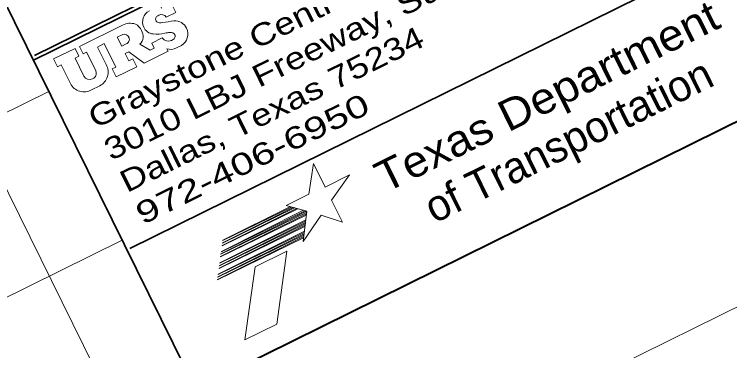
# Model space of a CAD drawing. Extents: x 2356606 to 2371222, y 6973096 to 6982644.
# Drawn here: x 2370176.5 to 2370607.9, y 6979196 to 6979398.7 of the extents above; entities that cross this region are included whole.
import ezdxf
from ezdxf.enums import TextEntityAlignment as Align

# ---------------------------------------------------------------- set-up
doc = ezdxf.new("R2010")
doc.units = 0
doc.header["$LTSCALE"] = 2
doc.layers.add('62', color=7, linetype='Continuous', lineweight=13)
doc.layers.add('63', color=7, linetype='Continuous', lineweight=13)

msp = doc.modelspace()

# ---------------------------------------------------------------- linework, layer by layer
at = {"layer": '62'}
for p, q in [((2369622.333, 6980406.659), (2370241.954, 6979151.173)), ((2371003.634, 6979415.568), (2358199.427, 6973096.266)), ((2370263.665, 6979398.139), (2370263.05, 6979397.836)), ((2370238.606, 6979384.905), (2370241.982, 6979386.571)), ((2370271.275, 6979382.972), (2370272.335, 6979383.54)), ((2370277.258, 6979379.982), (2370274.268, 6979378.507)), ((2370223.616, 6979359.868), (2370224.388, 6979360.249)), ((2370197.388, 6979352.221), (2358740.123, 6973697.678)), ((2370228.034, 6979355.685), (2370223.054, 6979353.231)), ((2370241.647, 6979262.543), (2358784.382, 6973608.002))]:
    msp.add_line(p, q, dxfattribs=at)
at = {"layer": '62', "lineweight": 35}
for p, q in [((2370021.757, 6979708.087), (2370285.907, 6979172.864)), ((2370772.563, 6979661.979), (2370188.769, 6979373.856)), ((2370601.161, 6979432.671), (2370246.201, 6979257.487))]:
    msp.add_line(p, q, dxfattribs=at)
at = {"layer": '62', "lineweight": 40}
msp.add_line((2370869.698, 6979460.986), (2358244.847, 6973230.201), dxfattribs=at)
at = {"layer": '62'}
for points in [[(2370265.161, 6979402.489), (2370265.378, 6979402.596), (2370264.774, 6979403.82), (2370270.561, 6979406.676), (2370273.942, 6979399.825), (2370268.155, 6979396.969)], [(2370225.423, 6979365.199), (2370220.137, 6979375.91), (2370218.015, 6979374.863), (2370215.777, 6979379.398), (2370241.818, 6979392.25)], [(2370244.07, 6979380.882), (2370241.273, 6979379.502), (2370238.606, 6979384.905)], [(2370252.242, 6979380.739), (2370258.53, 6979377.099), (2370260.942, 6979378.289), (2370259.418, 6979381.377), (2370265.783, 6979384.519)], [(2370210.421, 6979356.956), (2370204.849, 6979368.245), (2370202.534, 6979367.103), (2370200.201, 6979371.831), (2370213.125, 6979378.209), (2370215.458, 6979373.481), (2370213.143, 6979372.339), (2370218.525, 6979361.435)], [(2370268.541, 6979377.96), (2370269.303, 6979376.416), (2370254.835, 6979369.276), (2370245.489, 6979376.063), (2370243.463, 6979375.063), (2370245.654, 6979370.625), (2370248.065, 6979371.815), (2370250.399, 6979367.086), (2370237.957, 6979360.946), (2370235.576, 6979365.771), (2370237.794, 6979366.865), (2370230.794, 6979381.05), (2370226.646, 6979379.003), (2370231.885, 6979368.389)]]:
    msp.add_lwpolyline(points, dxfattribs=at)
for points in [[(2370356.998, 6979308.703), (2370354.183, 6979290.219), (2370340.423, 6979283.426), (2370352.86, 6979280.022), (2370350.698, 6979261.838), (2370361.606, 6979277.578), (2370374.364, 6979273.517), (2370367.885, 6979286.641), (2370378.66, 6979301.888), (2370363.949, 6979294.619)], [(2370301.158, 6979254.309), (2370352.651, 6979280.053), (2370352.85, 6979280.014), (2370352.756, 6979279.249), (2370301.158, 6979254.088)], [(2370301.389, 6979255.854), (2370350.831, 6979280.572), (2370351.874, 6979280.271), (2370301.377, 6979255.64)], [(2370301.873, 6979259.371), (2370346.655, 6979281.714), (2370347.573, 6979281.459), (2370301.879, 6979259.175)], [(2370302.111, 6979261.045), (2370344.615, 6979282.276), (2370345.551, 6979282.01), (2370302.074, 6979260.843)], [(2370302.326, 6979262.6), (2370342.758, 6979282.775), (2370343.681, 6979282.545), (2370302.322, 6979262.386)], [(2370300.419, 6979248.959), (2370352.247, 6979274.821), (2370352.144, 6979273.967), (2370300.4, 6979248.759)], [(2370300.946, 6979252.642), (2370352.681, 6979278.482), (2370352.57, 6979277.59), (2370300.955, 6979252.443)], [(2370299.968, 6979245.761), (2370351.856, 6979271.646), (2370351.753, 6979270.799), (2370299.961, 6979245.541)], [(2370300.182, 6979247.411), (2370352.054, 6979273.291), (2370351.958, 6979272.457), (2370300.188, 6979247.215)], [(2370299.206, 6979240.543), (2370351.252, 6979266.492), (2370351.149, 6979265.693), (2370299.204, 6979240.325)], [(2370299.448, 6979242.069), (2370351.429, 6979268.016), (2370351.326, 6979267.207), (2370299.432, 6979241.863)], [(2370299.005, 6979238.872), (2370351.046, 6979264.849), (2370350.938, 6979264.033), (2370298.971, 6979238.676)], [(2370321.742, 6979246.487), (2370315.593, 6979202.501), (2370334.786, 6979211.974), (2370340.921, 6979255.959)]]:
    msp.add_lwpolyline(points, close=True, dxfattribs=at)
for centre, radius, start, end in [((2370261.275, 6979394.235), 7.37, 116.59512, 205.42078), ((2370263.915, 6979395.847), 2.168, 113.49254, 206.41812), ((2370265.307, 6979395.241), 3.331, 31.2441, 119.53115), ((2370246.404, 6979383.148), 10.193, 71.68598, 116.74432), ((2370245.614, 6979385.55), 8.298, 24.22986, 61.23771), ((2370260.754, 6979393.405), 6.564, 200.83249, 265.92335), ((2370263.552, 6979395.413), 1.665, 198.57807, 225.70723), ((2370264.87, 6979399.008), 5.391, 242.59812, 282.13548), ((2370295.403, 6979220.264), 175.947, 97.38251, 99.61897), ((2370273.302, 6979386.757), 8.011, 26.74268, 93.62434), ((2370242.788, 6979383.581), 3.097, 18.24145, 105.09053), ((2370247.741, 6979385.415), 6.491, 313.90211, 33.05094), ((2370262.131, 6979409.27), 22.488, 265.29523, 283.19444), ((2370271.955, 6979360.094), 27.683, 93.25307, 99.75462), ((2370270.978, 6979385.129), 2.67, 22.69549, 102.85604), ((2370272.963, 6979386.988), 8.217, 301.50782, 24.23999), ((2370243.083, 6979383.538), 2.833, 290.38106, 20.93943), ((2370269.467, 6979387.075), 4.484, 214.75895, 293.78959), ((2370271.286, 6979385.526), 2.246, 297.83315, 16.35824), ((2370270.818, 6979384.377), 6.809, 250.46341, 300.44168), ((2370222.41, 6979363.246), 3.591, 303.41925, 32.96393), ((2370223.93, 6979363.864), 9.151, 296.64079, 29.63181), ((2370221.871, 6979363.252), 3.807, 208.49718, 297.28605), ((2370218.452, 6979360.909), 8.952, 206.21079, 300.93344)]:
    msp.add_arc(centre, radius, start, end, dxfattribs=at)
at = {"layer": '63'}
for p, q in [((2369622.333, 6980406.659), (2370241.954, 6979151.173)), ((2371003.634, 6979415.568), (2358199.427, 6973096.266)), ((2370197.388, 6979352.221), (2358740.123, 6973697.678)), ((2370241.647, 6979262.543), (2358784.382, 6973608.002))]:
    msp.add_line(p, q, dxfattribs=at)
at = {"layer": '63', "lineweight": 35}
for p, q in [((2370021.757, 6979708.087), (2370285.907, 6979172.864)), ((2370771.897, 6979659.152), (2370188.104, 6979371.029))]:
    msp.add_line(p, q, dxfattribs=at)
at = {"layer": '63', "lineweight": 40}
msp.add_line((2370869.698, 6979460.986), (2358244.847, 6973230.201), dxfattribs=at)
at = {"layer": '63'}
for points in [[(2370356.998, 6979308.703), (2370354.183, 6979290.219), (2370340.423, 6979283.426), (2370352.86, 6979280.022), (2370350.698, 6979261.838), (2370361.606, 6979277.578), (2370374.364, 6979273.517), (2370367.885, 6979286.641), (2370378.66, 6979301.888), (2370363.949, 6979294.619)], [(2370301.158, 6979254.309), (2370352.651, 6979280.053), (2370352.85, 6979280.014), (2370352.756, 6979279.249), (2370301.158, 6979254.088)], [(2370301.389, 6979255.854), (2370350.831, 6979280.572), (2370351.874, 6979280.271), (2370301.377, 6979255.64)], [(2370301.873, 6979259.371), (2370346.655, 6979281.714), (2370347.573, 6979281.459), (2370301.879, 6979259.175)], [(2370302.111, 6979261.045), (2370344.615, 6979282.276), (2370345.551, 6979282.01), (2370302.074, 6979260.843)], [(2370302.326, 6979262.6), (2370342.758, 6979282.775), (2370343.681, 6979282.545), (2370302.322, 6979262.386)], [(2370300.419, 6979248.959), (2370352.247, 6979274.821), (2370352.144, 6979273.967), (2370300.4, 6979248.759)], [(2370300.946, 6979252.642), (2370352.681, 6979278.482), (2370352.57, 6979277.59), (2370300.955, 6979252.443)], [(2370299.968, 6979245.761), (2370351.856, 6979271.646), (2370351.753, 6979270.799), (2370299.961, 6979245.541)], [(2370300.182, 6979247.411), (2370352.054, 6979273.291), (2370351.958, 6979272.457), (2370300.188, 6979247.215)], [(2370299.206, 6979240.543), (2370351.252, 6979266.492), (2370351.149, 6979265.693), (2370299.204, 6979240.325)], [(2370299.448, 6979242.069), (2370351.429, 6979268.016), (2370351.326, 6979267.207), (2370299.432, 6979241.863)], [(2370299.005, 6979238.872), (2370351.046, 6979264.849), (2370350.938, 6979264.033), (2370298.971, 6979238.676)], [(2370321.742, 6979246.487), (2370315.593, 6979202.501), (2370334.786, 6979211.974), (2370340.921, 6979255.959)]]:
    msp.add_lwpolyline(points, close=True, dxfattribs=at)

# ---------------------------------------------------------------- texts
at = {"layer": '62'}
for s, width, p in [('3010 LBJ Freeway, Suite 1300', 1.25, (2370234.848, 6979310.249)), ('Graystone Centre', 1.25, (2370225.312, 6979329.572)), ('Dallas, Texas 75234', 1.25, (2370244.384, 6979290.927)), ('972-406-6950', 1.4, (2370253.921, 6979271.604))]:
    msp.add_text(s, height=13.22, rotation=26.268, dxfattribs=dict(at, width=width)).set_placement(p)
at = {"layer": '62', "width": 1.1}
msp.add_text('Texas Department', height=18.76, rotation=26.268, dxfattribs=at).set_placement((2370501.79, 6979340.989), align=Align.CENTER)
at = {"layer": '62'}
msp.add_text('of Transportation', height=18.76, rotation=26.268, dxfattribs=at).set_placement((2370514.85, 6979314.368), align=Align.CENTER)
at = {"layer": '63', "width": 1.1}
msp.add_text('Texas Department', height=18.76, rotation=26.268, dxfattribs=at).set_placement((2370501.79, 6979340.989), align=Align.CENTER)
at = {"layer": '63'}
msp.add_text('of Transportation', height=18.76, rotation=26.268, dxfattribs=at).set_placement((2370514.85, 6979314.368), align=Align.CENTER)

doc.saveas('drawing.dxf')
